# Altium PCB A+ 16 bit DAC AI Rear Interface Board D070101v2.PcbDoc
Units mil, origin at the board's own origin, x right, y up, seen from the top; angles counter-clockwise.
Board outline 2600 x 10000 mil, 4 copper layers (Top Layer, GND, GND (Plane2), Bottom Layer), stack 61.2 mil thick; 6 components, 34 nets, 121 pads, 323 vias.
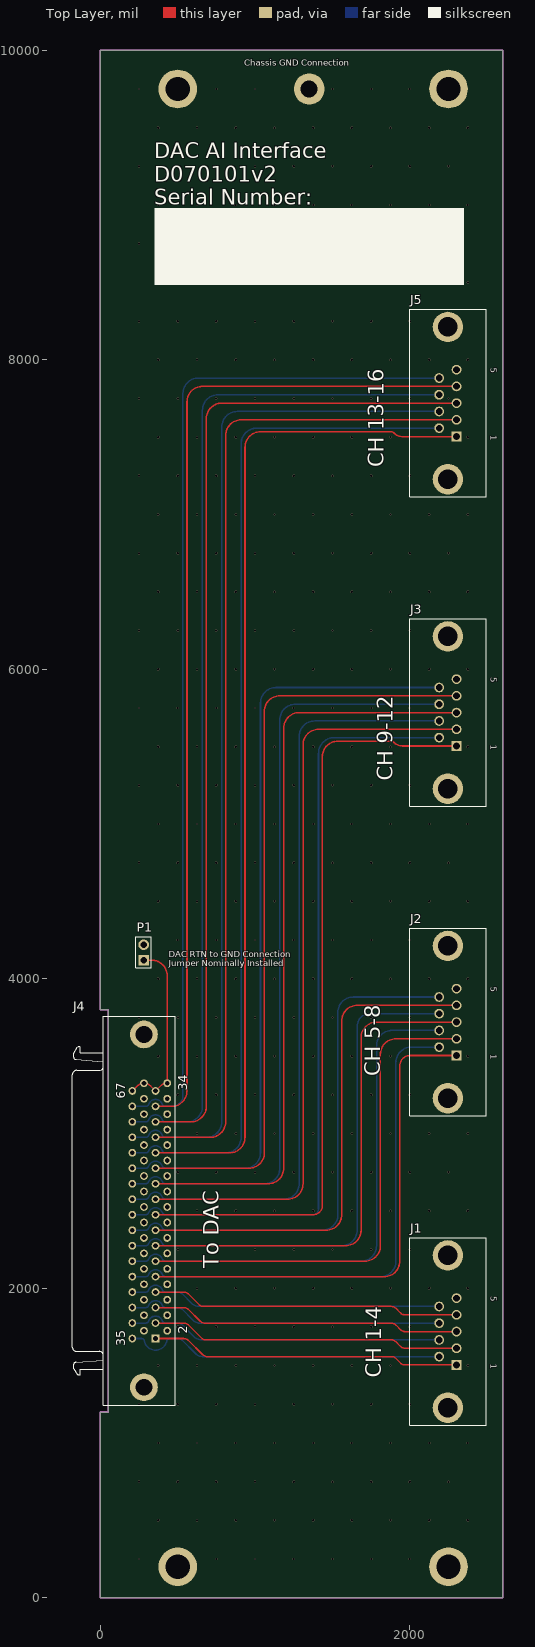
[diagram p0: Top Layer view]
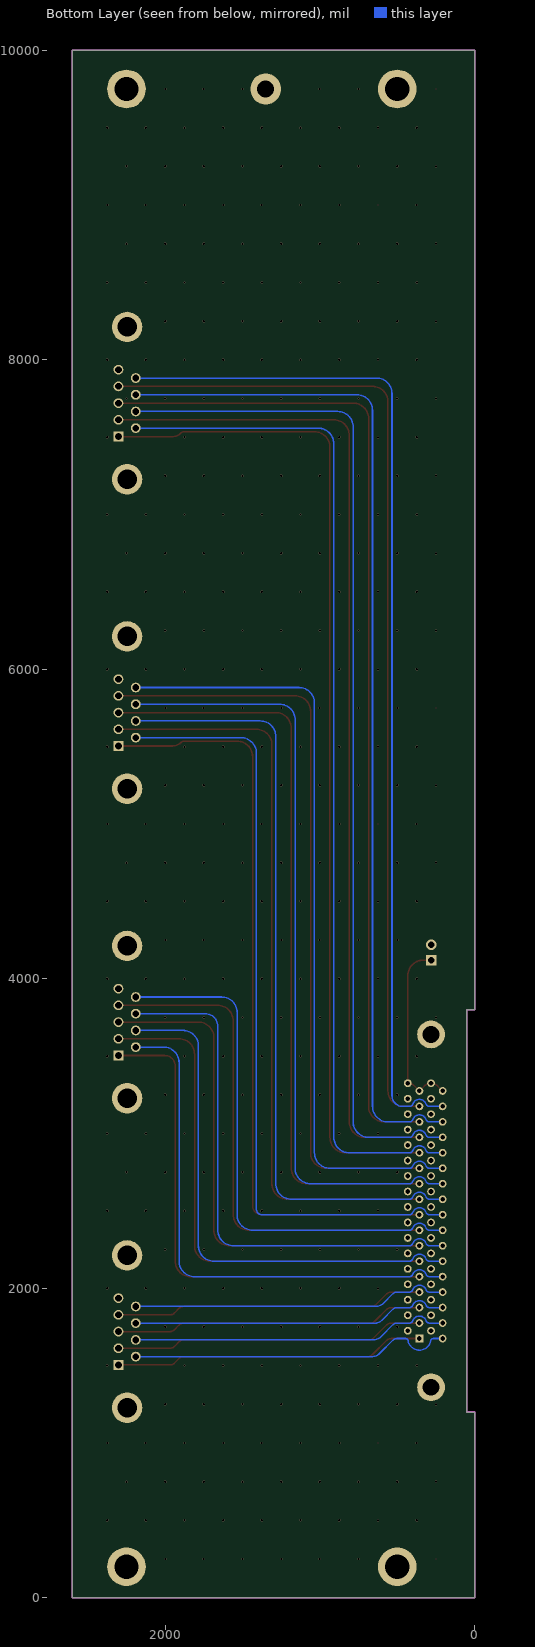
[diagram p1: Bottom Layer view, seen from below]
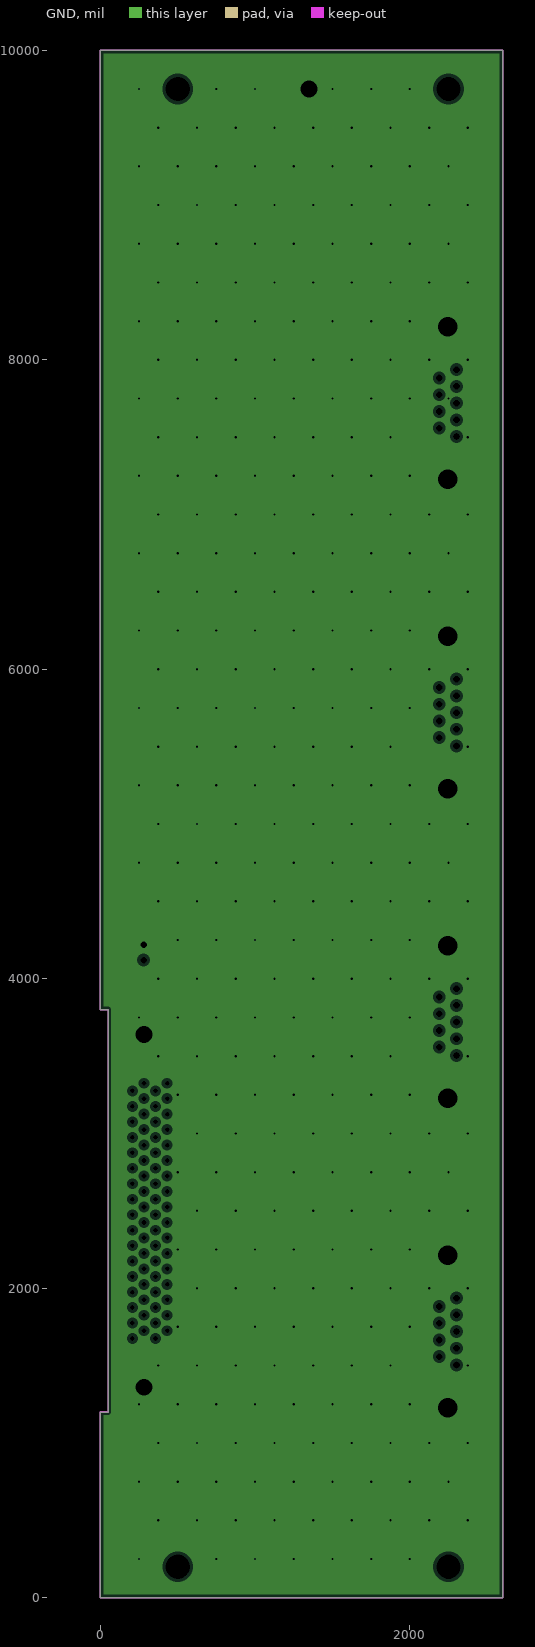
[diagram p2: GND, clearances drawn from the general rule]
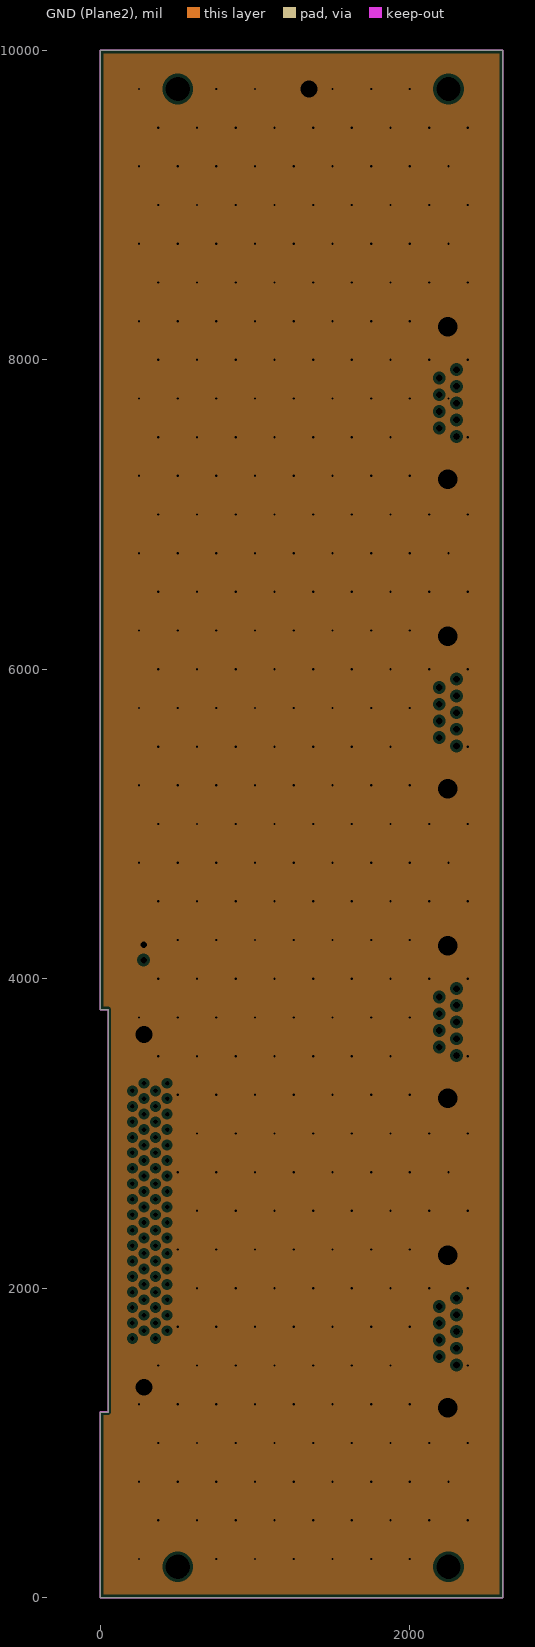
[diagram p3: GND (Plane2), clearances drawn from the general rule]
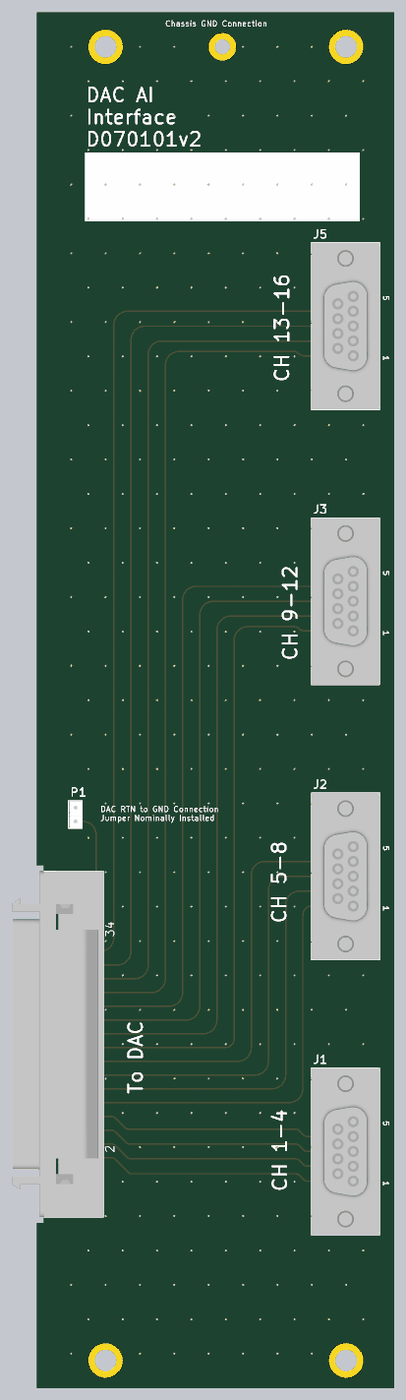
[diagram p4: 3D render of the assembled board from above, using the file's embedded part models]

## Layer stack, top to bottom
Top Solder: solder mask 0.4, Solder Resist, Dk 3.5
Top Layer: signal copper 1.4
Dielectric 1: prepreg 7.5, FR-4, Dk 4.2
GND: plane copper 1.4, net GND
Dielectric 3: prepreg 40.6, Dk 4.2
GND (Plane2): plane copper 1.4, net GND
Dielectric 2: prepreg 7.5, FR-4, Dk 4.2
Bottom Layer: signal copper 1.4
Bottom Solder: solder mask 0.4, Solder Resist, Dk 3.5

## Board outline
0,0 0,1200 50,1200 50,3800 0,3800 0,10000 2600,10000 2600,0

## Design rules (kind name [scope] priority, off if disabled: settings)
Clearance [All] p1: gap=10 ignorepadtopadclearanceinfootprint=FALSE except(0: Arc-Hole Track-Hole SMDPad-Hole THPad-Hole Via-Hole Fill-Hole Poly-Hole Region-Hole Text-Hole)
FabricationTestPointUsage TestPointUsage [All] p1: valid=0 allowmultiple=FALSE
FabricationTestpoint Testpoint [All] p1: side=3 testpointundercomponent=TRUE minsize=40 maxsize=100 preferedsize=60 minholesize=0 maxholesize=40 preferedholesize=32 testpointgrid=1 allowsidetop=TRUE allowsidebottom=TRUE usegrid=TRUE gridtolerance=0.01
HoleSize [All] p1: absolutevalues=TRUE maxlimit=200 minlimit=1 maxpercent=80.000 minpercent=20.000
PlaneClearance [All] p1: clearance=20
PlaneConnect [All] p1: planeconnectstyle=Direct reliefexpansion=20 reliefentries=4 reliefconductorwidth=10 reliefairgap=10
PolygonConnect [All] p1: connectstyle=Direct reliefconductorwidth=10 reliefentries=4 polygonreliefangle="90 Angle" airgapwidth=10
RoutingVias [All] p1: holewidth=20 width=40 viastyle="Through Hole" minholewidth=20 minwidth=40 maxholewidth=28 maxwidth=50
SolderMaskExpansion [All] p1: expansion=4
Width [All] p1: maxlimit=100 minlimit=10 preferedwidth=10
25 further rules are at their usual default settings.

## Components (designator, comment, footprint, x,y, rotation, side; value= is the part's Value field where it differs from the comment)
J1 "D9F" D9F 2246,1720 r270 top
J2 "D9F" D9F 2246,3720 r270 top
J3 "D9F" D9F 2246,5720 r270 top
J4 "787082-7" 787082-7 20,2500 r90 top
J5 "D9F" D9F 2246,7720 r270 top
P1 "Header 2" HDR1X2 280,4120 r90 top

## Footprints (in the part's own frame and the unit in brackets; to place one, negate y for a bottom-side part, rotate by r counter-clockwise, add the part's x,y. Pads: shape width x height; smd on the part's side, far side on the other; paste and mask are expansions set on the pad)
787082-7 [mm] "Connector; D Subminiature 050 Series; 68 Position; Right Angle"
  rect 1.27x1.27 hole 0.762: 1(-20.955,-8.555)
  round 1.27 hole 0.762: 2(-19.685,-10.46) 3(-18.415,-8.555) 4(-17.145,-10.46) 5(-15.875,-8.555) 6(-14.605,-10.46) 7(-13.335,-8.555) 8(-12.065,-10.46) 9(-10.795,-8.555) 10(-9.525,-10.46) 11(-8.255,-8.555) 12(-6.985,-10.46) 13(-5.715,-8.555) 14(-4.445,-10.46) 15(-3.175,-8.555) 16(-1.905,-10.46) 17(-0.635,-8.555) 18(0.635,-10.46) 19(1.905,-8.555) 20(3.175,-10.46) 21(4.445,-8.555) 22(5.715,-10.46) 23(6.985,-8.555) 24(8.255,-10.46) 25(9.525,-8.555) 26(10.795,-10.46) 27(12.065,-8.555) 28(13.335,-10.46) 29(14.605,-8.555) 30(15.875,-10.46) 31(17.145,-8.555) 32(18.415,-10.46) 33(19.685,-8.555) 34(20.955,-10.46) 35(-20.955,-4.745) 36(-19.685,-6.65) 37(-18.415,-4.745) 38(-17.145,-6.65) 39(-15.875,-4.745) 40(-14.605,-6.65) 41(-13.335,-4.745) 42(-12.065,-6.65) 43(-10.795,-4.745) 44(-9.525,-6.65) 45(-8.255,-4.745) 46(-6.985,-6.65) 47(-5.715,-4.745) 48(-4.445,-6.65) 49(-3.175,-4.745) 50(-1.905,-6.65) 51(-0.635,-4.745) 52(0.635,-6.65) 53(1.905,-4.745) 54(3.175,-6.65) 55(4.445,-4.745) 56(5.715,-6.65) 57(6.985,-4.745) 58(8.255,-6.65) 59(9.525,-4.745) 60(10.795,-6.65) 61(12.065,-4.745) 62(13.335,-6.65) 63(14.605,-4.745) 64(15.875,-6.65) 65(17.145,-4.745) 66(18.415,-6.65) 67(19.685,-4.745) 68(20.955,-6.65)
  round 4.55 hole 2.77: 69(-28.955,-6.65) 70(28.955,-6.65)
  silkscreen extent -31.95,-11.76 31.95,5.11, body extent -31.94,-11.79 31.94,5.08, height 9.51
D9F [mm]
  rect 1.6x1.6 hole 1.1: 1(5.486,1.422)
  round 1.6 hole 1.1: 2(2.743,1.422) 3(0.005,1.422) 4(-2.743,1.422) 5(-5.486,1.422) 6(4.115,-1.422) 7(1.372,-1.422) 8(-1.372,-1.422) 9(-4.115,-1.422)
  round 5 hole 3.2: 10(-12.497,0) 11(12.497,0)
  silkscreen extent -15.4,-6.3 15.4,6.3, body extent -15.4,-6.3 15.41,6.3, height 12.18
HDR1X2 [mm] "Connector; Header; 2 Position"
  rect 1.75x1.75 hole 1.1: 1(0,0)
  round 1.75 hole 1.1: 2(2.54,0)
  silkscreen extent -1.27,-1.27 3.81,1.27, body extent -1.14,-1.19 3.68,1.15, height 10.8

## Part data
J1 J2 J3 J5: "9 Position D-Sub Receptacle, Female Sockets Connector", Case/Package=Metal, Color=Black, Current Rating=6A, Flammability Rating="UL94 V-0", Manufacturer="TE Connectivity", Manufacturer Part Number=5747150-7, Max Operating Temperature=105°C, Max Supply Voltage (AC)=250V, Max Voltage Rating (DC)=250.25kV, Min Operating Temperature=-55°C, Package Quantity=17, Supplier Part Number 1=A34073-ND, Voltage Rating=125V
J4: library part "D68F 90deg", "68 Position D-Type Receptacle, Female Sockets Connector", Color=Black, Current Rating=1A, Flammability Rating="UL94 V-0", Manufacturer="TE Connectivity", Manufacturer Part Number=7870827, Max Operating Temperature=105°C, Min Operating Temperature=-55°C, Package Quantity=8, Supplier Part Number 1=A3321-ND, Voltage Rating=30V
P1: "Connector Header Through Hole 2 position 0.100\" (2.54mm)", Color=White, Contact Resistance=10mR, Current Rating=4A, Flammability Rating="UL94 V-0", Insulation Resistance=500GR, Manufacturer=Molex, Manufacturer Part Number=22-23-2021, Max Operating Temperature=75°C, Min Operating Temperature=0°C, Package Quantity=3000, Supplier Part Number 1=WM4200-ND, Voltage Rating=250V

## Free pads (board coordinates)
  round 200 hole 110: 0(1350,9750)
  round 250 hole 157.48: 0(2250,200) 1(2250,9750) 2(500,9750) 3(500,200)

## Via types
v1: diameter 15, hole 15, Top Layer to Bottom Layer, tented both sides, 323 vias

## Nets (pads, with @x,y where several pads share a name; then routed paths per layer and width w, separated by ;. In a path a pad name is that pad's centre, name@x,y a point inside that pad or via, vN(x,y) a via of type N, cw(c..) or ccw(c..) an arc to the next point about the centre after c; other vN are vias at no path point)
GND: J1.10 J1.11 J2.10 J2.11 J3.10 J3.11 J4.69 J4.70 J5.10 J5.11 P1.2 pad.0@1350,9750
  other v1: 250,250 750,250 1000,250 1250,250 1500,250 1750,250 2000,250 375,500 625,500 875,500 1125,500 1375,500 1625,500 1875,500 2125,500 2375,500 250,750 500,750 750,750 1000,750 1250,750 1500,750 1750,750 2000,750 2250,750 375,1000 625,1000 875,1000 1125,1000 1375,1000 1625,1000 1875,1000 2125,1000 2375,1000 250,1250 500,1250 750,1250 1000,1250 1250,1250 1500,1250 1750,1250 2000,1250 375,1500 625,1500 875,1500 1125,1500 1375,1500 1625,1500 1875,1500 2375,1500 500,1750 750,1750 1000,1750 1250,1750 1500,1750 1750,1750 2000,1750 625,2000 875,2000 1125,2000 1375,2000 1625,2000 1875,2000 2125,2000 2375,2000 500,2250 750,2250 1000,2250 1250,2250 1500,2250 1750,2250 2000,2250 625,2500 875,2500 1125,2500 1375,2500 1625,2500 1875,2500 2125,2500 2375,2500 500,2750 750,2750 1000,2750 1250,2750 1500,2750 1750,2750 2000,2750 2250,2750 625,3000 875,3000 1125,3000 1375,3000 1625,3000 1875,3000 2125,3000 2375,3000 500,3250 750,3250 1000,3250 1250,3250 1500,3250 1750,3250 2000,3250 375,3500 625,3500 875,3500 1125,3500 1375,3500 1625,3500 1875,3500 2375,3500 250,3750 500,3750 750,3750 1000,3750 1250,3750 1500,3750 1750,3750 2000,3750 375,4000 625,4000 875,4000 1125,4000 1375,4000 1625,4000 1875,4000 2125,4000 2375,4000 500,4250 750,4250 1000,4250 1250,4250 1500,4250 1750,4250 2000,4250 375,4500 625,4500 875,4500 1125,4500 1375,4500 1625,4500 1875,4500 2125,4500 2375,4500 250,4750 500,4750 750,4750 1000,4750 1250,4750 1500,4750 1750,4750 2000,4750 2250,4750 375,5000 625,5000 875,5000 1125,5000 1375,5000 1625,5000 1875,5000 2125,5000 2375,5000 250,5250 500,5250 750,5250 1000,5250 1250,5250 1500,5250 1750,5250 2000,5250 375,5500 625,5500 875,5500 1125,5500 1375,5500 1625,5500 1875,5500 2375,5500 250,5750 500,5750 750,5750 1000,5750 1250,5750 1500,5750 1750,5750 2000,5750 375,6000 625,6000 875,6000 1125,6000 1375,6000 1625,6000 1875,6000 2125,6000 2375,6000 250,6250 500,6250 750,6250 1000,6250 1250,6250 1500,6250 1750,6250 2000,6250 375,6500 625,6500 875,6500 1125,6500 1375,6500 1625,6500 1875,6500 2125,6500 2375,6500 250,6750 500,6750 750,6750 1000,6750 1250,6750 1500,6750 1750,6750 2000,6750 2250,6750 375,7000 625,7000 875,7000 1125,7000 1375,7000 1625,7000 1875,7000 2125,7000 2375,7000 250,7250 500,7250 750,7250 1000,7250 1250,7250 1500,7250 1750,7250 2000,7250 375,7500 625,7500 875,7500 1125,7500 1375,7500 1625,7500 1875,7500 2375,7500 250,7750 500,7750 750,7750 1000,7750 1250,7750 1500,7750 1750,7750 2000,7750 2250,7750 375,8000 625,8000 875,8000 1125,8000 1375,8000 1625,8000 1875,8000 2125,8000 2375,8000 250,8250 500,8250 750,8250 1000,8250 1250,8250 1500,8250 1750,8250 2000,8250 375,8500 625,8500 875,8500 1125,8500 1375,8500 1625,8500 1875,8500 2125,8500 2375,8500 250,8750 500,8750 750,8750 1000,8750 1250,8750 1500,8750 1750,8750 2000,8750 2250,8750 375,9000 625,9000 875,9000 1125,9000 1375,9000 1625,9000 1875,9000 2125,9000 2375,9000 250,9250 500,9250 750,9250 1000,9250 1250,9250 1500,9250 1750,9250 2000,9250 2250,9250 375,9500 625,9500 875,9500 1125,9500 1375,9500 1625,9500 1875,9500 2125,9500 2375,9500 250,9750 750,9750 1000,9750 1500,9750 1750,9750 2000,9750
INPUTN1: J1.6 J4.35 | length 2102.7
  Bottom Layer w10: J4.35 268.12,1675 cw(c268.12,1659.12) 284,1659.12 ; 283.53,1659.02 ccw(c356.81,1675) 430.11,1659.12 cw(c445.99,1659.12) 445.99,1675 503,1675 cw(c503,1641.2) 526.9,1665.1 613,1579 ccw(c664.21,1630.21) 658.66,1558 J1.6
INPUTN2: J1.7 J4.37 | length 2062.9
  Bottom Layer w10: J4.37 294,1775 ; 294.04,1775 ccw(c294,1794.31) 310.92,1785.01 319.07,1800.13 cw(c356.81,1775) 394.55,1800.13 402.7,1785.02 ccw(c419.62,1794.31) 419.58,1775 503,1775 cw(c503,1741.2) 526.9,1765.1 605,1687 ccw(c656.21,1738.21) 650.66,1666 J1.7
INPUTN3: J1.8 J4.39 | length 2059.6
  Bottom Layer w10: J4.39 294,1875 ; 294.04,1875 ccw(c294,1894.31) 310.92,1885.01 319.07,1900.13 cw(c356.81,1875) 394.55,1900.13 402.7,1885.02 ccw(c419.62,1894.31) 419.58,1875 503,1875 cw(c503,1841.2) 526.9,1865.1 599,1793 ; 599.04,1793.04 ccw(c648.21,1846.21) 642.66,1774 J1.8
INPUTN4: J1.9 J4.41 | length 2056.2
  Bottom Layer w10: J4.41 294,1975 ; 294.04,1975 ccw(c294,1994.31) 310.92,1985.01 319.07,2000.13 cw(c356.81,1975) 394.55,2000.13 402.7,1985.02 ccw(c419.62,1994.31) 419.58,1975 503,1975 cw(c503,1941.2) 526.9,1965.1 588.79,1903.21 ccw(c640,1954.43) 640,1882 J1.9
INPUTN5: J2.6 J4.43 | length 3419.4
  Bottom Layer w10: J4.43 294,2075 ; 294.04,2075 ccw(c294,2094.31) 310.92,2085.01 319.07,2100.13 cw(c356.81,2075) 394.55,2100.13 402.7,2085.02 ccw(c419.62,2094.31) 419.58,2075 1810,2075 ccw(c1810,2175) 1910,2175 1910,3458 cw(c2010,3458) 2010,3558 J2.6
INPUTN6: J2.7 J4.45 | length 3427.4
  Bottom Layer w10: J4.45 294,2175 ; 294.04,2175 ccw(c294,2194.31) 310.92,2185.01 319.07,2200.13 cw(c356.81,2175) 394.55,2200.13 402.7,2185.02 ccw(c419.62,2194.31) 419.58,2175 1685,2175 ccw(c1685,2275) 1785,2275 1785,3566 cw(c1885,3566) 1885,3666 J2.7
INPUTN7: J2.8 J4.47 | length 3444
  Bottom Layer w10: J4.47 294,2275 ; 294.04,2275 ccw(c294,2294.31) 310.92,2285.01 319.07,2300.13 cw(c356.81,2275) 394.55,2300.13 402.7,2285.02 ccw(c419.62,2294.31) 419.58,2275 1560,2275 ccw(c1560,2375) 1660,2375 1660,3694 cw(c1740,3694) 1740,3774 J2.8
INPUTN8: J2.9 J4.49 | length 3443.4
  Bottom Layer w10: J4.49 294,2375 ; 294.04,2375 ccw(c294,2394.31) 310.92,2385.01 319.07,2400.13 cw(c356.81,2375) 394.55,2400.13 402.7,2385.02 ccw(c419.62,2394.31) 419.58,2375 1435,2375 ccw(c1435,2475) 1535,2475 1535,3782 cw(c1635,3782) 1635,3882 J2.9
INPUTN9: J3.6 J4.51 | length 5047.3
  Bottom Layer w10: J4.51 294,2475 ; 294.04,2475 ccw(c294,2494.31) 310.92,2485.01 319.07,2500.13 cw(c356.81,2475) 394.55,2500.13 402.7,2485.02 ccw(c419.62,2494.31) 419.58,2475 1375,2475 ccw(c1375,2510) 1410,2510 1410,5458 cw(c1510,5458) 1510,5558 J3.6
INPUTN10: J3.7 J4.53 | length 5027.4
  Bottom Layer w10: J4.53 294,2575 ; 294.04,2575 ccw(c294,2594.31) 310.92,2585.01 319.07,2600.13 cw(c356.81,2575) 394.55,2600.13 402.7,2585.02 ccw(c419.62,2594.31) 419.58,2575 1185,2575 ccw(c1185,2675) 1285,2675 1285,5566 cw(c1385,5566) 1385,5666 J3.7
INPUTN11: J3.8 J4.55 | length 5035.4
  Bottom Layer w10: J4.55 294,2675 ; 294.04,2675 ccw(c294,2694.31) 310.92,2685.01 319.07,2700.13 cw(c356.81,2675) 394.55,2700.13 402.7,2685.02 ccw(c419.62,2694.31) 419.58,2675 1060,2675 ccw(c1060,2775) 1160,2775 1160,5674 cw(c1260,5674) 1260,5774 J3.8
INPUTN12: J3.9 J4.57 | length 5043.4
  Bottom Layer w10: J4.57 294,2775 ; 294.04,2775 ccw(c294,2794.31) 310.92,2785.01 319.07,2800.13 cw(c356.81,2775) 394.55,2800.13 402.7,2785.02 ccw(c419.62,2794.31) 419.58,2775 935,2775 ccw(c935,2875) 1035,2875 1035,5782 cw(c1135,5782) 1135,5882 J3.9
INPUTN13: J4.59 J5.6 | length 6619.4
  Bottom Layer w10: J4.59 294,2875 ; 294.04,2875 ccw(c294,2894.31) 310.92,2885.01 319.07,2900.13 cw(c356.81,2875) 394.55,2900.13 402.7,2885.02 ccw(c419.62,2894.31) 419.58,2875 810,2875 ccw(c810,2975) 910,2975 910,7458 cw(c1010,7458) 1010,7558 1265,7558 J5.6
INPUTN14: J4.61 J5.7 | length 6627.5
  Bottom Layer w10: J4.61 294,2975 ; 294.04,2975 ccw(c294,2994.31) 310.92,2985.01 319.07,3000.13 cw(c356.81,2975) 394.55,3000.13 402.7,2985.02 ccw(c419.62,2994.31) 419.58,2975 685,2975 ccw(c685,3075) 785,3075 785,7566 cw(c885,7566) 885,7666 1050,7666 J5.7
INPUTN15: J4.63 J5.8 | length 6635.5
  Bottom Layer w10: J4.63 294,3075 ; 294.04,3075 ccw(c294,3094.31) 310.92,3085.01 319.07,3100.13 cw(c356.81,3075) 394.55,3100.13 402.7,3085.02 ccw(c419.62,3094.31) 419.58,3075 560,3075 ccw(c560,3175) 660,3175 660,7674 cw(c760,7674) 760,7774 915,7774 J5.8
INPUTN16: J4.65 J5.9 | length 6656.3
  Bottom Layer w10: J4.65 294,3175 ; 294.04,3175 ccw(c294,3194.31) 310.92,3185.01 319.07,3200.13 cw(c356.81,3175) 394.55,3200.13 402.7,3185.02 ccw(c419.62,3194.31) 419.58,3175 464,3175 ccw(c464,3245) 534,3245 534,7782 cw(c634,7782) 634,7882 J5.9
INPUTP1: J1.1 J4.1 | length 2012.1
  Top Layer w10: J4.1 540,1675 cw(c540,1634.03) 566.74,1665.07 ; 568.97,1663 ccw(c540,1634.03) 566.74,1665.07 ; 661.92,1569.89 566.74,1665.07 ; 662.03,1570 ccw(c691,1598.97) 691,1558 1881.09,1558 ; 1881,1558 cw(c1881,1517.03) 1881.09,1558 ; 1909.97,1546 ccw(c1881,1517.03) 1881.09,1558 ; 1909.99,1546.01 1940.01,1515.99 ; 1940.03,1516 ccw(c1969,1544.97) 1969,1504 J1.1
INPUTP2: J1.2 J4.3 | length 2008.8
  Top Layer w10: J4.3 540,1775 cw(c540,1734.03) 566.74,1765.07 ; 568.97,1763 ccw(c540,1734.03) 566.74,1765.07 ; 653.92,1677.89 566.74,1765.07 ; 654.03,1678 ccw(c683,1706.97) 683,1666 1881.12,1666 ; 1881.03,1666 cw(c1881.03,1625.03) 1881.12,1666 ; 1940.01,1623.99 1910,1654 ccw(c1881.03,1625.03) 1881.12,1666 ; 1940.03,1624 ccw(c1969,1652.97) 1969,1612 J1.2
INPUTP3: J1.3 J4.5 | length 2005.2
  Top Layer w10: J4.5 540,1875 cw(c540,1834.03) 566.74,1865.07 ; 568.97,1863 ccw(c540,1834.03) 566.74,1865.07 ; 645.81,1786 566.74,1865.07 ; 646.03,1786 ccw(c675,1814.97) 675,1774 1881.03,1774 ; 1881.03,1773.8 cw(c1881.03,1732.83) 1910,1761.8 1940.01,1731.79 ; 1940.03,1731.8 ccw(c1969,1760.77) 1969,1719.8 J1.3
INPUTP4: J1.4 J4.7 | length 2002.1
  Top Layer w10: J4.7 531,1975 540,1975 cw(c540,1934.03) 566.74,1965.07 ; 568.97,1963 ccw(c540,1934.03) 566.74,1965.07 ; J1.4 1968.97,1828 cw(c1968.97,1868.97) 1940,1840 1910,1870 ccw(c1881.03,1841.03) 1881.03,1882 667,1882 cw(c667,1922.97) 638.03,1894 637.81,1894 566.74,1965.07
INPUTP5: J2.1 J4.9 | length 3302.5
  Top Layer w10: J4.9 1835,2075 ccw(c1835,2175) 1935,2175 1935,3437 cw(c2002,3437) 2002,3504 J2.1
INPUTP6: J2.2 J4.11 | length 3296.3
  Top Layer w10: J4.11 1710,2175 ccw(c1710,2275) 1810,2275 1810,3512 cw(c1910,3512) 1910,3612 J2.2
INPUTP7: J2.3 J4.13 | length 3304.2
  Top Layer w10: J4.13 1585,2275 ccw(c1585,2375) 1685,2375 1685,3619.8 cw(c1785,3619.8) 1785,3719.8 J2.3
INPUTP8: J2.4 J4.15 | length 3312.3
  Top Layer w10: J4.15 1460,2375 ccw(c1460,2475) 1560,2475 1560,3728 cw(c1660,3728) 1660,3828 J2.4
INPUTP9: J3.1 J4.17 | length 4945.2
  Top Layer w10: J4.17 1375,2475 ccw(c1375,2535) 1435,2535 1435,5435.23 cw(c1535,5435.23) 1535,5535.23 1875,5535.23 cw(c1875,5500) 1899.96,5524.86 ; 1899.91,5524.91 ccw(c1950.39,5575.39) 1899.96,5524.86 ; J3.1 1950.39,5504 cw(c1950.39,5575.39) 1899.96,5524.86
INPUTP10: J3.2 J4.19 | length 4896.3
  Top Layer w10: J4.19 1210,2575 ccw(c1210,2675) 1310,2675 1310,5512 cw(c1410,5512) 1410,5612 J3.2
INPUTP11: J3.3 J4.21 | length 4904.2
  Top Layer w10: J4.21 1085,2675 ccw(c1085,2775) 1185,2775 1185,5619.8 cw(c1285,5619.8) 1285,5719.8 J3.3
INPUTP12: J3.4 J4.23 | length 4912.3
  Top Layer w10: J4.23 960,2775 ccw(c960,2875) 1060,2875 1060,5728 cw(c1160,5728) 1160,5828 J3.4
INPUTP13: J4.25 J5.1 | length 6530.4
  Top Layer w10: J4.25 835,2875 ccw(c835,2975) 935,2975 935,7435.23 cw(c1035,7435.23) 1035,7535.23 1875,7535.23 ; J5.1 1947,7504 cw(c1947,7566.77) 1902.62,7522.38 1900,7525 ccw(c1875.31,7500.31) 1875.31,7535.23 ; 1875,7535.23 cw(c1875,7500) 1875.31,7535.23 ; 1875,7535.23 cw(c1875,7500.21) 1875.31,7535.23 ; 1875,7535.23 1875.31,7535.23 ; 1875.31,7535.23 cw(c1875,7500) 1876.04,7535.21 ccw(c1875,7500.21) 1875.31,7535.23
INPUTP14: J4.27 J5.2 | length 6496.3
  Top Layer w10: J4.27 710,2975 ccw(c710,3075) 810,3075 810,7512 cw(c910,7512) 910,7612 J5.2
INPUTP15: J4.29 J5.3 | length 6504.2
  Top Layer w10: J4.29 585,3075 ccw(c585,3175) 685,3175 685,7619.8 cw(c785,7619.8) 785,7719.8 J5.3
INPUTP16: J4.31 J5.4 | length 6512.3
  Top Layer w10: J4.31 460,3175 ccw(c460,3275) 560,3275 560,7728 cw(c660,7728) 660,7828 J5.4
INPUTRTN: J4.33 J4.34 J4.67 J4.68 P1.1 | length 1183.2
  Top Layer w10: J4.67 239.13,3307.32 cw(c281.81,3264.64) J4.68 cw(c281.81,3264.64) 324.49,3307.32 J4.33 389.13,3307.32 cw(c431.81,3264.64) J4.34 431.81,4020 ccw(c331.81,4020) 331.81,4120 P1.1
pads on no net: J1.5 J2.5 J3.5 J4.2 J4.4 J4.6 J4.8 J4.10 J4.12 J4.14 J4.16 J4.18 J4.20 J4.22 J4.24 J4.26 J4.28 J4.30 J4.32 J4.36 J4.38 J4.40 J4.42 J4.44 J4.46 J4.48 J4.50 J4.52 J4.54 J4.56 J4.58 J4.60 J4.62 J4.64 J4.66 J5.5

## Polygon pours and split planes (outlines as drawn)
no net on Top Layer "Top Layer-No Net" (solid, pour order 6): 20,9980
GND on GND (split plane): 2579.9,20.1 20.1,20.1 20.1,1179.9 50,1179.9 53.92,1180.29 57.69,1181.43 61.17,1183.29 64.21,1185.79 66.71,1188.83 68.57,1192.31 69.71,1196.08 70.1,1200 70.1,3800 69.71,3803.92 68.57,3807.69 66.71,3811.17 64.21,3814.21 61.17,3816.71 57.69,3818.57 53.92,3819.71 50,3820.1 20.1,3820.1 20.1,9979.9 2579.9,9979.9
GND on GND (Plane2) (split plane): 2579.9,20.1 20.1,20.1 20.1,1179.9 50,1179.9 53.92,1180.29 57.69,1181.43 61.17,1183.29 64.21,1185.79 66.71,1188.83 68.57,1192.31 69.71,1196.08 70.1,1200 70.1,3800 69.71,3803.92 68.57,3807.69 66.71,3811.17 64.21,3814.21 61.17,3816.71 57.69,3818.57 53.92,3819.71 50,3820.1 20.1,3820.1 20.1,9979.9 2579.9,9979.9

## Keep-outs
Keep-Out Layer:
  the board outline again, w10

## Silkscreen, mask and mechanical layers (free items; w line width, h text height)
Top Overlay:
  rectangle: 350,8482 2350,8982
  text "Chassis GND Connection" at 930,9900 h40
  text "DAC AI Interface / D070101v2 / Serial Number:" at 350,9002 h100
  text "CH 13-16" at 1830,7305 h100 r90
  text "CH 9-12" at 1890,5280 h100 r90
  text "DAC RTN to GND Connection / Jumper Nominally Installed" at 441,4080 h40
  text "CH 5-8" at 1810,3370 h100 r90
  text "To DAC" at 765,2130 h100 r90
  text "CH 1-4" at 1815,1420 h100 r90
Mechanical 1:
  lines w10: 2600,0 0,0 0,1200 50,1200 50,2500 50,3800 0,3800 0,10000 2600,10000

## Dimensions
500,9750 to 2250,9750 on Mechanical 1
0,15250 to 500,9750 on Mechanical 1
-78.74,15250 to 500,200 on Mechanical 1
-78.74,15250 to 500,9750 on Mechanical 1
2250,9750 to 2250,200 on Mechanical 1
